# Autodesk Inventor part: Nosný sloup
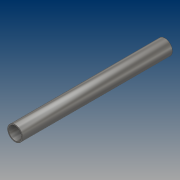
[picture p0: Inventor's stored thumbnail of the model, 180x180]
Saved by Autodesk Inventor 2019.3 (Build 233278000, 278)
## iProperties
Created: 2019-03
Part Number: Nosný sloup
Material: Ocel, měkká
Document SubType Name: Modeling
Designer: B-hon
Density: 7.85 g/cm^3
Appearance: Pololeštěná
Author: B-hon
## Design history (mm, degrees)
sketch "Náčrt1"
  geometry: C1 r 35 at (0, 0); C2 r 30 at (0, 0); 1 further point
  constraints: 2 centre point, 1 coincident
  dimensions: "d0" = 70 diameter of C1; "d1" = 5 radial gap between concentric circles of C1 C2
extrude "Vysunutí1" new body sketch "Náčrt1" distance "d2" = 693.25; taper "d3" = 0 deg
node "Těleso1"
